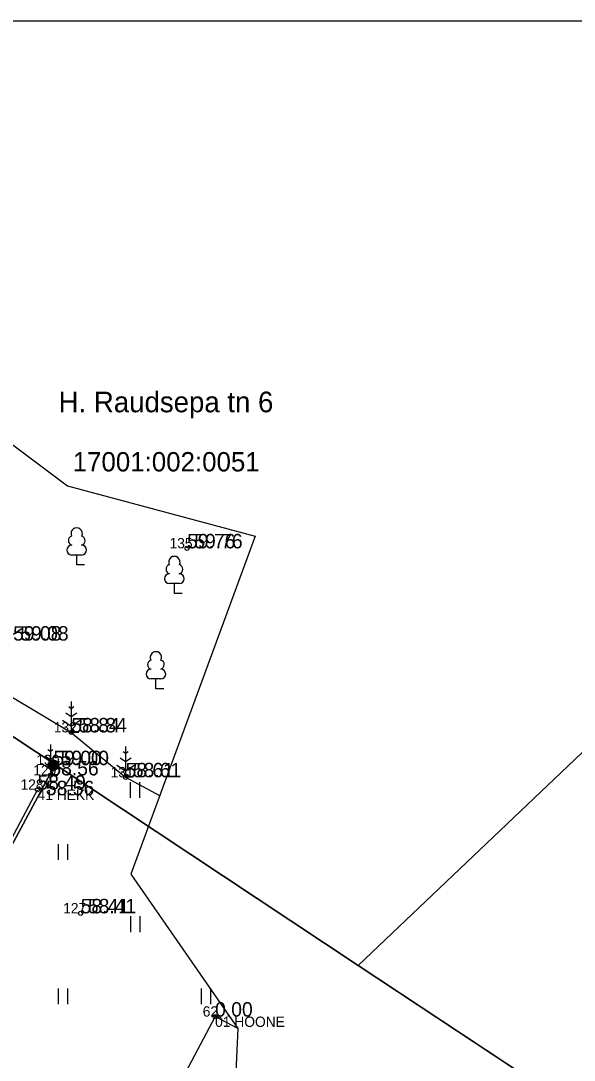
# Model space of a CAD drawing. Extents: x 640891 to 641083, y 6456526 to 6456669.
# Drawn here: x 640984.2 to 641011.1, y 6456618.4 to 6456668.8 of the extents above; entities that cross this region are included whole.
import ezdxf

# ---------------------------------------------------------------- set-up
doc = ezdxf.new("R2010")
doc.units = 0
for name, color, linetype in [('100koma2', 7, 'Continuous'), ('HALJASTUS', 7, 'Continuous'), ('HOONE', 7, 'Continuous'), ('KORGUS', 7, 'Continuous'), ('MOOTKORG', 7, 'Continuous'), ('MOOTMPUNKT', 7, 'Continuous'), ('MOOTNR', 7, 'Continuous'), ('MOOTPIIR', 7, 'Continuous'), ('PIIR', 7, 'Continuous'), ('PUU', 7, 'Continuous'), ('RAJATIS', 7, 'Continuous'), ('VORMISTUS', 7, 'Continuous')]:
    doc.layers.add(name, color=color, linetype=linetype)

msp = doc.modelspace()

# ---------------------------------------------------------------- linework, layer by layer
at = {"layer": 'HALJASTUS'}
for p, q in [((640989.531, 6456631.881), (640989.531, 6456631.12)), ((640989.986, 6456631.881), (640989.986, 6456631.12)), ((640986.045, 6456628.881), (640986.045, 6456628.119)), ((640986.5, 6456628.881), (640986.5, 6456628.119)), ((640989.545, 6456625.381), (640989.545, 6456624.619)), ((640990, 6456625.381), (640990, 6456624.619)), ((640986.045, 6456621.881), (640986.045, 6456621.119)), ((640986.5, 6456621.881), (640986.5, 6456621.119)), ((640992.975, 6456621.881), (640992.975, 6456621.119)), ((640993.43, 6456621.881), (640993.43, 6456621.119))]:
    msp.add_line(p, q, dxfattribs=at)
for points in [[(640946.505, 6456648.924), (640957.822, 6456644.615), (640966.207, 6456640.588), (640973.066, 6456642.422), (640986.679, 6456634.293)], [(640986.679, 6456634.293), (640989.309, 6456632.118), (640990.985, 6456631.223)], [(640962.925, 6456576.62), (640957.383, 6456579.521), (640966.138, 6456596.056), (640972.417, 6456607.592), (640977.059, 6456616.501), (640985.041, 6456631.518)]]:
    msp.add_lwpolyline(points, dxfattribs=at)
at = {"layer": 'HOONE'}
for p, q in [((640993.648, 6456620.522), (640991.616, 6456616.709)), ((640994.744, 6456619.938), (640993.648, 6456620.522))]:
    msp.add_line(p, q, dxfattribs=at)
at = {"layer": 'KORGUS'}
for centre in [(640992.289, 6456643.212), (640986.679, 6456634.293), (640985.811, 6456632.707), (640985.663, 6456632.21), (640989.309, 6456632.118), (640987.133, 6456625.526)]:
    msp.add_circle(centre, 0.1, dxfattribs=at)
at = {"layer": 'MOOTMPUNKT'}
for centre in [(640992.289, 6456643.212), (640986.679, 6456634.293), (640985.811, 6456632.707), (640985.663, 6456632.21), (640989.309, 6456632.118), (640985.041, 6456631.518), (640987.133, 6456625.526), (640993.648, 6456620.522)]:
    msp.add_circle(centre, 0.1, dxfattribs=at)
at = {"layer": 'MOOTPIIR'}
msp.add_lwpolyline([(640924.706, 6456598.502), (640938.233, 6456631.58), (640948.873, 6456653.866), (640953.873, 6456657.504), (640964.983, 6456662.356), (640986.497, 6456646.235), (640995.587, 6456643.81), (640989.565, 6456627.418), (640994.744, 6456619.938), (640993.953, 6456602.696)], dxfattribs=at)
at = {"layer": 'PIIR'}
for points in [[(641039.59, 6456660.086), (641000.58, 6456623), (640985.89, 6456632.73), (640960.76, 6456649.34), (640935.64, 6456665.95), (640931.367, 6456668.776)], [(641029.209, 6456604.07), (641000.58, 6456623), (641039.59, 6456660.086)]]:
    msp.add_lwpolyline(points, dxfattribs=at)
for points in [[(640957.22, 6456579.32), (640930.79, 6456593.51), (640960.76, 6456649.34), (640985.89, 6456632.73)], [(640983.63, 6456565.13), (640957.22, 6456579.32), (640985.89, 6456632.73), (641000.58, 6456623), (641011.01, 6456616.1)]]:
    msp.add_lwpolyline(points, close=True, dxfattribs=at)
at = {"layer": 'PUU'}
for p, q in [((640987.18, 6456642.889), (640986.7, 6456642.889)), ((640986.94, 6456642.414), (640986.94, 6456642.889)), ((640987.32, 6456642.414), (640986.94, 6456642.414)), ((640991.913, 6456641.503), (640991.433, 6456641.503)), ((640991.673, 6456641.028), (640991.673, 6456641.503)), ((640992.053, 6456641.028), (640991.673, 6456641.028)), ((640983.856, 6456639.048), (640984.28, 6456639.331)), ((640991.018, 6456636.883), (640990.538, 6456636.883)), ((640990.778, 6456636.408), (640990.778, 6456636.883)), ((640991.158, 6456636.408), (640990.778, 6456636.408)), ((640986.679, 6456635.793), (640986.679, 6456634.293)), ((640986.679, 6456635.043), (640986.412, 6456635.22)), ((640986.679, 6456635.443), (640986.554, 6456635.526)), ((640986.803, 6456635.526), (640986.679, 6456635.443)), ((640986.945, 6456635.22), (640986.679, 6456635.043)), ((640986.254, 6456634.882), (640986.679, 6456634.599)), ((640986.679, 6456634.599), (640987.103, 6456634.882)), ((640987.039, 6456634.293), (640986.679, 6456634.293)), ((640985.663, 6456633.71), (640985.663, 6456632.21)), ((640989.309, 6456633.618), (640989.309, 6456632.118)), ((640985.663, 6456632.96), (640985.396, 6456633.137)), ((640985.663, 6456633.36), (640985.539, 6456633.443)), ((640985.787, 6456633.443), (640985.663, 6456633.36)), ((640985.93, 6456633.137), (640985.663, 6456632.96)), ((640989.309, 6456633.268), (640989.185, 6456633.351)), ((640989.434, 6456633.351), (640989.309, 6456633.268)), ((640985.239, 6456632.799), (640985.663, 6456632.516)), ((640985.663, 6456632.516), (640986.087, 6456632.799)), ((640988.885, 6456632.708), (640989.309, 6456632.425)), ((640989.309, 6456632.868), (640989.043, 6456633.046)), ((640989.576, 6456633.046), (640989.309, 6456632.868)), ((640989.309, 6456632.425), (640989.733, 6456632.708)), ((640986.023, 6456632.21), (640985.663, 6456632.21)), ((640989.669, 6456632.118), (640989.309, 6456632.118))]:
    msp.add_line(p, q, dxfattribs=at)
for centre, radius, start, end in [((640986.94, 6456643.934), 0.277, 332.5799, 207.4201), ((640986.77, 6456643.587), 0.233, 109.0217, 253.1415), ((640987.11, 6456643.587), 0.233, 286.8508, 70.9859), ((640986.703, 6456643.127), 0.238, 90.0016, 269.3953), ((640987.178, 6456643.127), 0.238, 270.6047, 89.9984), ((640991.673, 6456642.548), 0.277, 332.5799, 207.4201), ((640991.503, 6456642.201), 0.233, 109.0217, 253.1415), ((640991.843, 6456642.201), 0.233, 286.8508, 70.9859), ((640991.435, 6456641.741), 0.238, 90.0016, 269.3953), ((640991.91, 6456641.741), 0.238, 270.6047, 89.9984), ((640990.778, 6456637.928), 0.277, 332.5799, 207.4201), ((640990.608, 6456637.58), 0.233, 109.0217, 253.1415), ((640990.948, 6456637.58), 0.233, 286.8508, 70.9859), ((640990.541, 6456637.12), 0.238, 90.0016, 269.3953), ((640991.016, 6456637.12), 0.238, 270.6047, 89.9984)]:
    msp.add_arc(centre, radius, start, end, dxfattribs=at)
at = {"layer": 'RAJATIS'}
for radius in [0.25, 0.225, 0.2, 0.175, 0.15, 0.125, 0.1, 0.075, 0.05, 0.025]:
    msp.add_circle((640985.811, 6456632.707), radius, dxfattribs=at)
at = {"layer": 'VORMISTUS'}
msp.add_line((640890.598, 6456668.776), (641082.733, 6456668.776), dxfattribs=at)

# ---------------------------------------------------------------- texts
at = {"layer": '100koma2'}
for s, p in [('41 HEKK', (640985.041, 6456631.018)), ('01 HOONE', (640993.648, 6456620.022))]:
    msp.add_text(s, height=0.5, dxfattribs=at).set_placement(p)
at = {"layer": 'KORGUS'}
for s, p in [('59.76', (640992.639, 6456643.212)), ('59.08', (640984.206, 6456638.741)), ('58.84', (640987.029, 6456634.293)), ('59.00', (640986.161, 6456632.707)), ('58.61', (640989.659, 6456632.118)), ('58.56', (640985.448, 6456631.248)), ('58.41', (640987.483, 6456625.526))]:
    msp.add_text(s, height=0.7, dxfattribs=at).set_placement(p)
at = {"layer": 'MOOTKORG'}
for s, p in [('59.76', (640992.289, 6456643.212)), ('59.08', (640983.856, 6456638.741)), ('58.84', (640986.679, 6456634.293)), ('59.00', (640985.811, 6456632.707)), ('58.56', (640985.663, 6456632.21)), ('58.61', (640989.309, 6456632.118)), ('58.49', (640985.041, 6456631.518)), ('58.41', (640987.133, 6456625.526)), ('0.00', (640993.648, 6456620.522))]:
    msp.add_text(s, height=0.7, dxfattribs=at).set_placement(p)
at = {"layer": 'MOOTNR'}
for s, p in [('135', (640991.439, 6456643.212)), ('132', (640985.829, 6456634.293)), ('130', (640984.986, 6456632.707)), ('129', (640984.838, 6456632.21)), ('131', (640988.584, 6456632.118)), ('128', (640984.216, 6456631.518)), ('127', (640986.283, 6456625.526)), ('62', (640993.048, 6456620.522))]:
    msp.add_text(s, height=0.5, dxfattribs=at).set_placement(p)
at = {"layer": 'PIIR'}
for s, height, p in [('H. Raudsepa tn 6', 1.00002, (640986.064, 6456649.806)), ('17001:002:0051', 0.9375, (640986.745, 6456646.939))]:
    msp.add_text(s, height=height, dxfattribs=at).set_placement(p)

doc.saveas('drawing.dxf')
